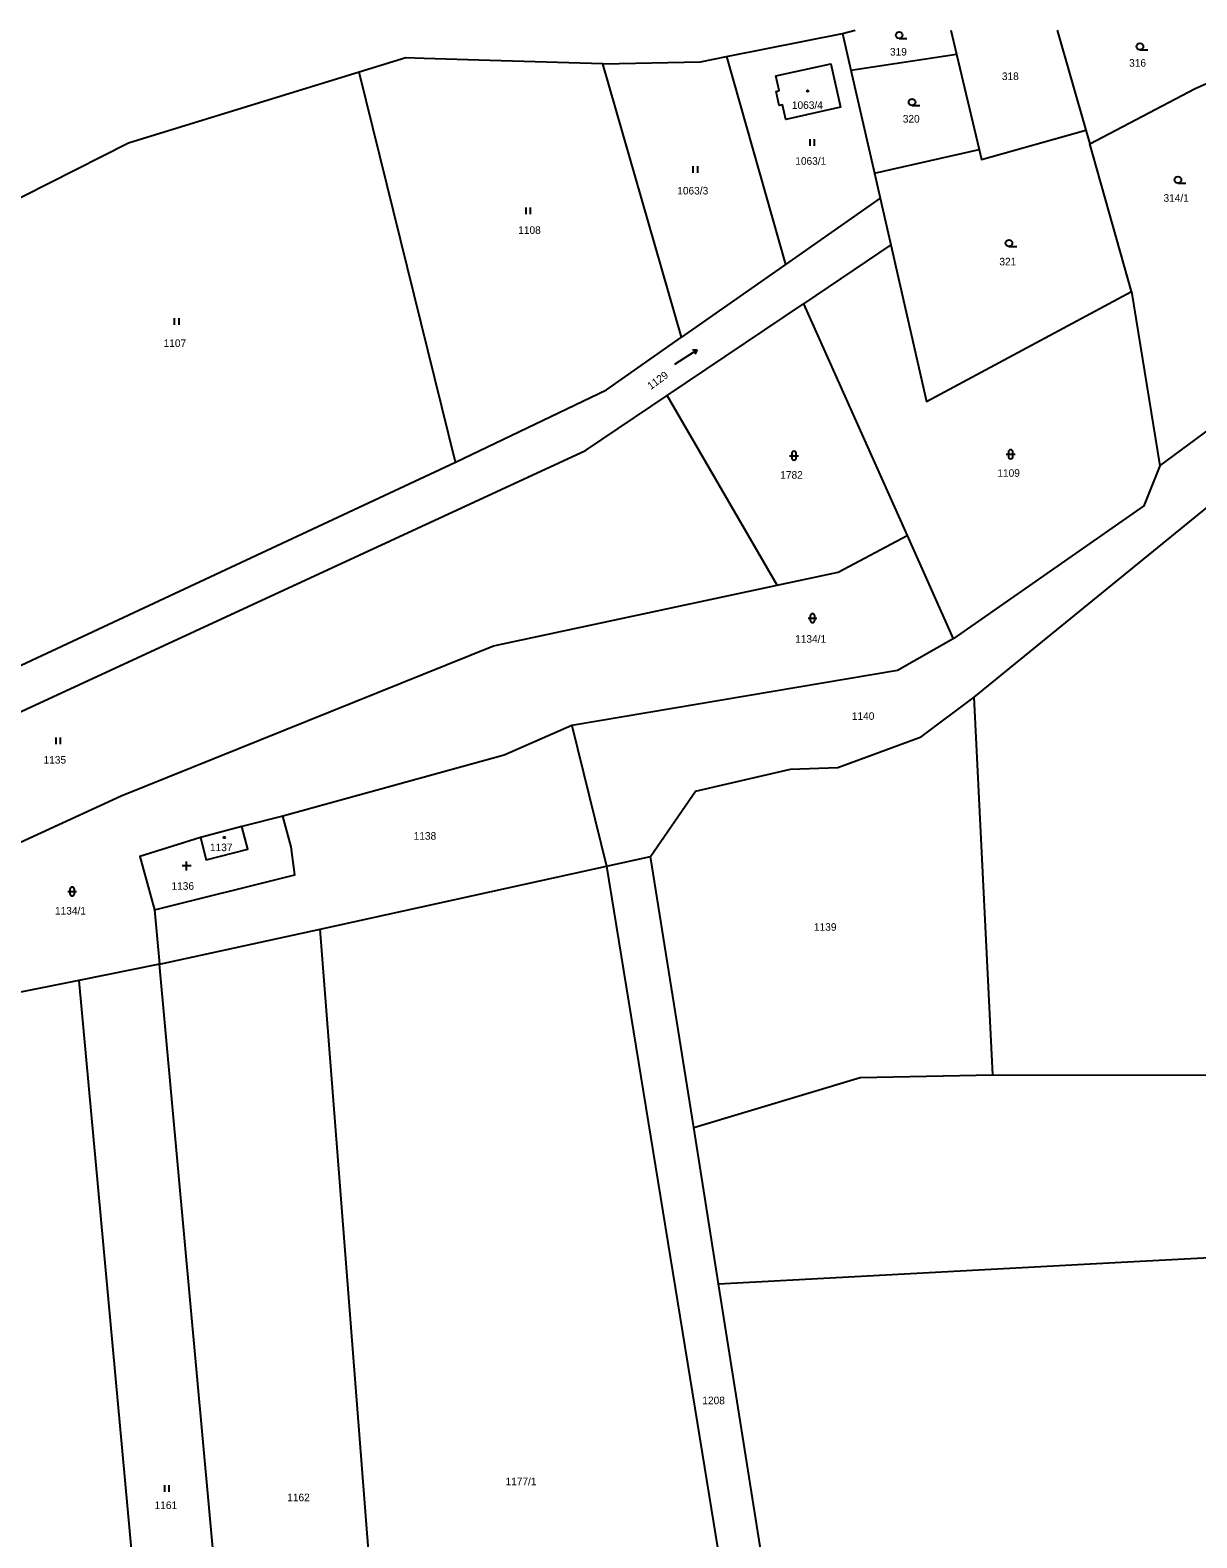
# Model space of a CAD drawing. Extents: x -520431 to -517205, y -1075927 to -1074013.
# Drawn here: x -518376.5 to -518114.5, y -1074353.4 to -1074014.8 of the extents above; entities that cross this region are included whole.
import ezdxf

# ---------------------------------------------------------------- set-up
doc = ezdxf.new("R2010")
doc.units = 0
for name, color, linetype in [('Hranice parcel', 7, 'Continuous'), ('Parcelní čísla', 7, 'Continuous'), ('Značky budov', 7, 'Continuous'), ('Značky kultur', 7, 'Continuous')]:
    doc.layers.add(name, color=color, linetype=linetype)

msp = doc.modelspace()

# ---------------------------------------------------------------- linework, layer by layer
at = {"layer": 'Hranice parcel'}
for p, q in [((-518220.07, -1074020.72), (-518194.04, -1074015.55)), ((-518194.04, -1074015.55), (-518191.19, -1074014.78)), ((-518194.04, -1074015.55), (-518192.16, -1074023.79)), ((-518169.76, -1074014.78), (-518168.48, -1074020.18)), ((-518145.83, -1074014.78), (-518139.43, -1074037.26)), ((-518114.84, -1074027.88), (-518095.56, -1074019.24)), ((-518247.88, -1074022.35), (-518273.23, -1074021.62)), ((-518230.19, -1074083.74), (-518247.88, -1074022.35)), ((-518220.07, -1074020.72), (-518206.89, -1074067.41)), ((-518192.16, -1074023.79), (-518168.48, -1074020.18)), ((-518168.48, -1074020.18), (-518163.37, -1074041.62)), ((-518302.61, -1074024.23), (-518354.42, -1074040.18)), ((-518280.93, -1074111.82), (-518302.61, -1074024.23)), ((-518192.16, -1074023.79), (-518186.89, -1074046.89)), ((-518138.55, -1074040.34), (-518114.84, -1074027.88)), ((-518354.42, -1074040.18), (-518384.03, -1074055.15)), ((-518139.43, -1074037.26), (-518138.55, -1074040.34)), ((-518186.89, -1074046.89), (-518163.37, -1074041.62)), ((-518129.14, -1074073.5), (-518138.55, -1074040.34)), ((-518186.89, -1074046.89), (-518185.61, -1074052.49)), ((-518185.61, -1074052.49), (-518206.89, -1074067.41)), ((-518185.61, -1074052.49), (-518183.21, -1074062.99)), ((-518183.21, -1074062.99), (-518202.85, -1074076.23)), ((-518206.89, -1074067.41), (-518230.19, -1074083.74)), ((-518129.14, -1074073.5), (-518122.83, -1074112.63)), ((-518233.45, -1074096.86), (-518202.85, -1074076.23)), ((-518202.85, -1074076.23), (-518179.56, -1074128.28)), ((-518164.48, -1074164.56), (-518065.32, -1074083.78)), ((-518122.83, -1074112.63), (-518093.12, -1074090.64)), ((-518208.72, -1074139.47), (-518233.45, -1074096.86)), ((-518379.64, -1074157.9), (-518280.93, -1074111.82)), ((-518179.56, -1074128.28), (-518169.18, -1074151.47)), ((-518160.31, -1074249.43), (-518164.48, -1074164.56)), ((-518254.84, -1074170.96), (-518247.02, -1074202.58)), ((-518319.71, -1074191.36), (-518328.92, -1074193.64)), ((-518328.92, -1074193.64), (-518338.2, -1074196.11)), ((-518311.32, -1074216.67), (-518247.02, -1074202.58)), ((-518247.02, -1074202.58), (-518237.15, -1074200.42)), ((-518227.41, -1074261.24), (-518237.15, -1074200.42)), ((-518348.54, -1074212.38), (-518347.42, -1074224.58)), ((-518347.42, -1074224.58), (-518311.32, -1074216.67)), ((-518347.42, -1074224.58), (-518365.52, -1074228.22)), ((-518221.87, -1074296.35), (-518227.41, -1074261.24))]:
    msp.add_line(p, q, dxfattribs=at)
for points in [[(-518273.23, -1074021.62), (-518287.97, -1074021.14), (-518292.13, -1074021), (-518302.61, -1074024.23)], [(-518247.88, -1074022.35), (-518225.93, -1074021.88), (-518220.07, -1074020.72)], [(-518209.01, -1074025.07), (-518196.69, -1074022.33), (-518194.49, -1074032.08), (-518206.78, -1074034.84), (-518207.53, -1074031.55), (-518208.26, -1074031.72), (-518208.99, -1074028.54), (-518208.25, -1074028.37), (-518209.01, -1074025.07)], [(-518163.37, -1074041.62), (-518162.85, -1074043.8), (-518139.43, -1074037.26)], [(-518183.21, -1074062.99), (-518175.17, -1074098.22), (-518129.14, -1074073.5)], [(-518280.93, -1074111.82), (-518247.06, -1074095.57), (-518230.19, -1074083.74)], [(-518495.42, -1074174.04), (-518429.31, -1074177.39), (-518409.68, -1074177.01), (-518390.4, -1074173.28), (-518251.79, -1074109.22), (-518233.45, -1074096.86)], [(-518122.83, -1074112.63), (-518126.36, -1074121.59), (-518169.18, -1074151.47)], [(-518208.72, -1074139.47), (-518195.03, -1074136.55), (-518179.56, -1074128.28)], [(-518486.24, -1074216.69), (-518409.76, -1074211.47), (-518356, -1074186.74), (-518272.43, -1074153.07), (-518208.72, -1074139.47)], [(-518169.18, -1074151.47), (-518181.7, -1074158.62), (-518254.84, -1074170.96)], [(-518237.15, -1074200.42), (-518227.04, -1074185.71), (-518205.76, -1074180.75), (-518195.14, -1074180.4), (-518176.38, -1074173.47), (-518164.48, -1074164.56)], [(-518254.84, -1074170.96), (-518270.03, -1074177.61), (-518319.71, -1074191.36)], [(-518160.31, -1074249.43), (-518042.84, -1074249.49), (-517973.88, -1074184.44)], [(-518348.54, -1074212.38), (-518317.04, -1074204.49), (-518317.89, -1074198.2), (-518319.71, -1074191.36)], [(-518338.2, -1074196.11), (-518336.96, -1074201.15), (-518327.61, -1074198.71), (-518328.92, -1074193.64)], [(-518338.2, -1074196.11), (-518351.81, -1074200.41), (-518348.54, -1074212.38)], [(-518247.02, -1074202.58), (-518225.04, -1074337.64), (-518209.02, -1074436.12)], [(-518293.29, -1074449.3), (-518300.51, -1074356.16), (-518311.32, -1074216.67)], [(-518322.37, -1074498.2), (-518334.9, -1074361.39), (-518347.42, -1074224.58)], [(-518365.52, -1074228.22), (-518457.89, -1074246.76), (-518509.31, -1074244.66)], [(-518365.52, -1074228.22), (-518353, -1074364.02), (-518340.51, -1074499.6)], [(-518227.41, -1074261.24), (-518190.06, -1074250.03), (-518160.31, -1074249.43)], [(-518221.87, -1074296.35), (-518130.08, -1074291.45), (-517982.16, -1074283.63), (-517979.79, -1074303.75), (-517969.62, -1074302.45)], [(-518206.41, -1074393.49), (-518210.84, -1074366.18), (-518221.87, -1074296.35)]]:
    msp.add_lwpolyline(points, dxfattribs=at)
at = {"layer": 'Značky budov'}
for centre in [(-518201.86, -1074028.45), (-518332.85, -1074196.11)]:
    msp.add_circle(centre, 0.175, dxfattribs=at)
at = {"layer": 'Značky kultur'}
for p, q in [((-518181.33, -1074016.67), (-518179.58, -1074016.67)), ((-518127.27, -1074019.22), (-518125.52, -1074019.22)), ((-518178.45, -1074031.72), (-518176.7, -1074031.72)), ((-518201.32, -1074040.77), (-518201.32, -1074039.27)), ((-518200.32, -1074040.77), (-518200.32, -1074039.27)), ((-518227.56, -1074046.82), (-518227.56, -1074045.32)), ((-518226.56, -1074046.82), (-518226.56, -1074045.32)), ((-518118.74, -1074049.14), (-518116.99, -1074049.14)), ((-518265.1, -1074056.13), (-518265.1, -1074054.63)), ((-518264.1, -1074056.13), (-518264.1, -1074054.63)), ((-518156.68, -1074063.37), (-518154.93, -1074063.37)), ((-518344.03, -1074080.97), (-518344.03, -1074079.47)), ((-518343.03, -1074080.97), (-518343.03, -1074079.47)), ((-518231.71, -1074089.84), (-518226.67, -1074086.57)), ((-518226.67, -1074086.57), (-518227.77, -1074086.69)), ((-518226.67, -1074086.57), (-518227.22, -1074087.53)), ((-518205.96, -1074110.36), (-518203.96, -1074110.36)), ((-518205.46, -1074109.86), (-518205.46, -1074110.86)), ((-518204.46, -1074110.86), (-518204.46, -1074109.86)), ((-518157.31, -1074110.03), (-518155.31, -1074110.03)), ((-518156.81, -1074109.53), (-518156.81, -1074110.53)), ((-518155.81, -1074110.53), (-518155.81, -1074109.53)), ((-518201.79, -1074146.85), (-518199.79, -1074146.85)), ((-518201.29, -1074146.35), (-518201.29, -1074147.35)), ((-518200.29, -1074147.35), (-518200.29, -1074146.35)), ((-518370.65, -1074175.15), (-518370.65, -1074173.65)), ((-518369.65, -1074175.15), (-518369.65, -1074173.65)), ((-518340.34, -1074202.51), (-518342.34, -1074202.51)), ((-518341.34, -1074203.51), (-518341.34, -1074201.51)), ((-518368.03, -1074208.25), (-518366.03, -1074208.25)), ((-518367.53, -1074207.75), (-518367.53, -1074208.75)), ((-518366.53, -1074208.75), (-518366.53, -1074207.75)), ((-518346.26, -1074343.06), (-518346.26, -1074341.56)), ((-518345.26, -1074343.06), (-518345.26, -1074341.56))]:
    msp.add_line(p, q, dxfattribs=at)
for centre in [(-518181.33, -1074015.92), (-518127.27, -1074018.47), (-518178.45, -1074030.97), (-518118.74, -1074048.39), (-518156.68, -1074062.62)]:
    msp.add_circle(centre, 0.75, dxfattribs=at)
for centre, start, end in [((-518204.96, -1074109.86), 0, 180), ((-518204.96, -1074110.86), 180, 359.9879), ((-518156.31, -1074109.53), 0, 180), ((-518156.31, -1074110.53), 180, 359.9879), ((-518200.79, -1074146.35), 0, 180), ((-518200.79, -1074147.35), 180, 359.9879), ((-518367.03, -1074207.75), 0, 180), ((-518367.03, -1074208.75), 180, 359.9879)]:
    msp.add_arc(centre, 0.5, start, end, dxfattribs=at)

# ---------------------------------------------------------------- texts
at = {"layer": 'Parcelní čísla'}
for s, p in [('319', (-518183.4, -1074020.49)), ('316', (-518129.7, -1074023)), ('318', (-518158.27, -1074025.99)), ('1063/4', (-518205.42, -1074032.47)), ('320', (-518180.52, -1074035.54)), ('1063/1', (-518204.66, -1074045.02)), ('1063/3', (-518231.16, -1074051.69)), ('314/1', (-518121.98, -1074053.33)), ('1108', (-518266.87, -1074060.54)), ('321', (-518158.83, -1074067.62)), ('1107', (-518346.49, -1074085.94)), ('1782', (-518208.03, -1074115.52)), ('1109', (-518159.28, -1074115.1)), ('1134/1', (-518204.7, -1074152.37)), ('1140', (-518191.96, -1074169.69)), ('1135', (-518373.46, -1074179.52)), ('1138', (-518290.35, -1074196.61)), ('1137', (-518336.09, -1074199.18)), ('1136', (-518344.73, -1074207.86)), ('1134/1', (-518370.89, -1074213.42)), ('1139', (-518200.47, -1074217.06)), ('1208', (-518225.53, -1074323.4)), ('1177/1', (-518269.73, -1074341.6)), ('1162', (-518318.74, -1074345.19)), ('1161', (-518348.52, -1074346.94))]:
    msp.add_text(s, height=1.7, dxfattribs=at).set_placement(p)
msp.add_text('1129', height=1.7, rotation=36, dxfattribs=at).set_placement((-518237.1, -1074095.62))

doc.saveas('drawing.dxf')
